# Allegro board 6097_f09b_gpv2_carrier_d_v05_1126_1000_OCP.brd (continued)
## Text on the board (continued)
User.45: DETAIL F | DETAIL A | DETAIL C | DETAIL E | DETAIL B | DETAIL D | FIGURE | SIZE | 8.0 | 9.84 | 10.0 | 22.0 | 40.0 | 41.0 | 67.0 | 107.0 | 33.0 | 38.0 | 39.0 | 46.0 | 49.0 | 56.0 | 65.0 | 85.0 | 122.0 | 158.0 | 34.0x26.0 | 48.0x20.0 | 59.0x33.0 | 63.0x20.0 | 54.0x38.0 | 189.0x126.0 | DRILL CHART: TOP to BOTTOM | ALL UNITS ARE IN MILS | TOLERANCE | +3.0/-3.0 | +2.0/-2.0 | +0.0/-10.0 | +3.0/-0.0 | +2.0/-0.0 | +4.0/-4.0 | PLATED | NON-PLATED | QTY | 25 | 32 | 64 | 542 | 5574 | 40 | 7 | 4 | 12 | 5 | 2 | 1 | 80
